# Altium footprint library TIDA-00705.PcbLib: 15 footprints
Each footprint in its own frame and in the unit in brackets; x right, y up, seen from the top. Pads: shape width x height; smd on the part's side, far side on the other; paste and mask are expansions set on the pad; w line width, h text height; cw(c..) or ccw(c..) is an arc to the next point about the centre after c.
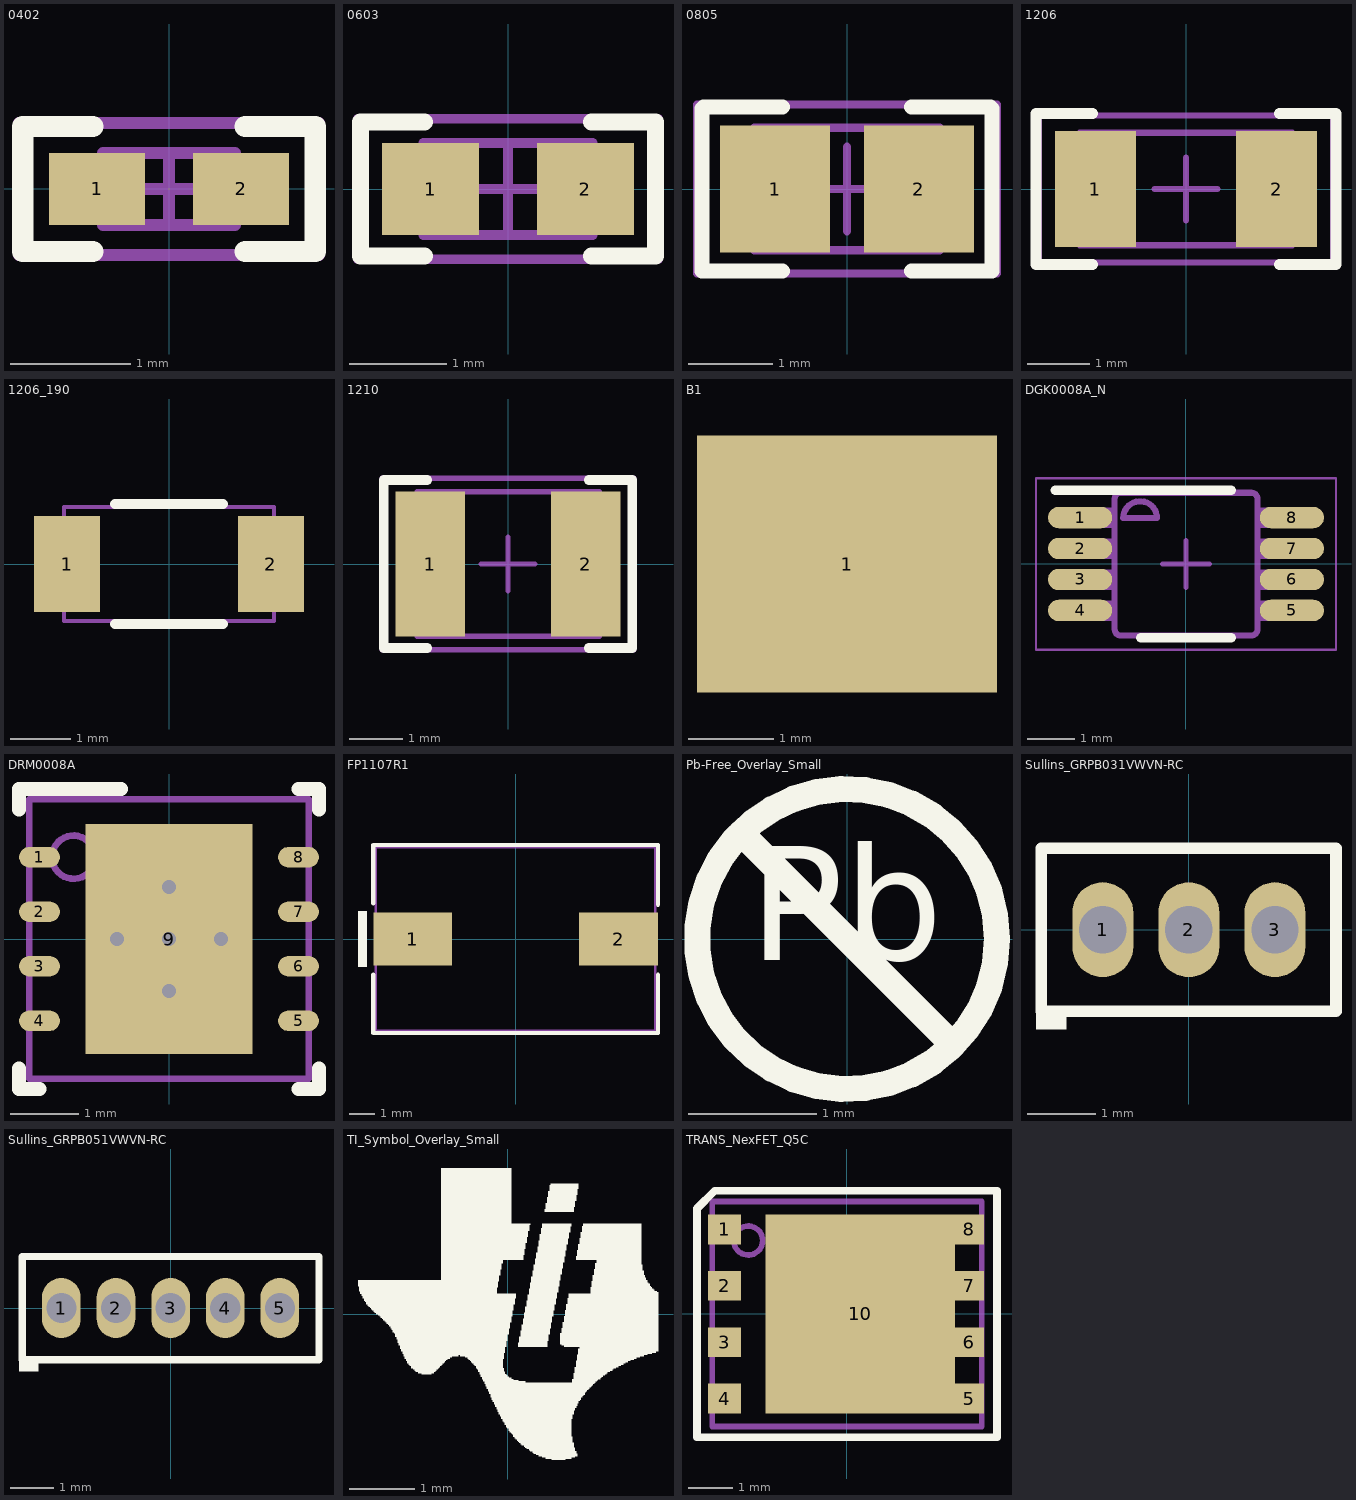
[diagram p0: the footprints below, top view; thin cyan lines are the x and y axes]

## 0402 [mm] "0402 from SM-752 data"
height 0.6
pads (2):
  rect 0.8x0.6 smd: 1(-0.6,0) 2(0.6,0)
Top Overlay:
  lines w0.178: -0.635,-0.521 -1.219,-0.521 -1.219,0.521 -0.635,0.521 ; 0.635,-0.521 1.219,-0.521 1.219,0.521 0.635,0.521
Mechanical 5:
  lines w0.1: -1.25,-0.55 1.25,-0.55 1.25,0.55 -1.25,0.55 -1.25,-0.55
  text ".Designator" at 0.864,0.381 h0.76
Mechanical 13:
  lines w0.1: -0.35,-0.3 -0.35,0.3 ; 0.35,-0.3 0.35,0.3 ; -0.55,-0.3 -0.55,0.3 0.55,0.3 0.55,-0.3 -0.55,-0.3
Mechanical 15:
  lines w0.1: -0.3,0 0.3,0 ; 0,-0.3 0,0.3 ; -1.25,-0.55 -1.25,0.55 1.25,0.55 1.25,-0.55 -1.25,-0.55
3D body: height 0.6, standoff 0, extent -0.549,-0.299 -0.351,0.299
3D body: height 0.6, standoff 0, extent -0.349,-0.299 0.349,0.299
3D body: height 0.6, standoff 0, extent 0.351,-0.299 0.549,0.299

## 0603 [mm] "0603 from SM-752 data"
height 1
pads (2):
  rect 1x0.95 smd: 1(-0.8,0) 2(0.8,0)
Top Overlay:
  lines w0.178: -0.864,-0.691 -1.524,-0.691 -1.524,0.693 -0.864,0.693 ; 0.864,-0.691 1.524,-0.691 1.524,0.693 0.864,0.693
Mechanical 5:
  lines w0.1: -1.55,-0.725 -1.55,0.725 1.55,0.725 1.55,-0.725 -1.55,-0.725
  text ".Designator" at 0.813,0.432 h0.76
Mechanical 13:
  lines w0.1: -0.55,-0.475 -0.55,0.475 ; 0.55,-0.475 0.55,0.475 ; -0.875,-0.475 0.875,-0.475 0.875,0.475 -0.875,0.475 -0.875,-0.475
Mechanical 15:
  lines w0.1: -0.475,0 0.475,0 ; 0,-0.475 0,0.475 ; -1.55,-0.725 1.55,-0.725 1.55,0.725 -1.55,0.725 -1.55,-0.725
3D body: height 1, standoff 0, extent -0.874,-0.474 -0.551,0.474
3D body: height 1, standoff 0, extent -0.549,-0.474 0.549,0.474
3D body: height 1, standoff 0, extent 0.551,-0.474 0.874,0.474

## 0805 [mm] "0805 from SM-752 data"
height 1.45
pads (2):
  rect 1.3x1.5 smd: 1(-0.85,0) 2(0.85,0)
Top Overlay:
  lines w0.178: -0.762,-0.968 -1.717,-0.968 -1.717,0.95 -1.699,0.968 -0.762,0.968 ; 0.762,-0.968 1.717,-0.968 1.717,0.95 1.699,0.968 0.762,0.968
Mechanical 5:
  lines w0.1: -1.775,-1 1.775,-1 1.775,1 -1.775,1 -1.775,-1
  text ".Designator" at 1.041,0.381 h0.76
Mechanical 13:
  lines w0.1: -0.65,-0.725 -0.65,0.725 ; 0.65,-0.725 0.65,0.725 ; -1.1,-0.725 1.1,-0.725 1.1,0.725 -1.1,0.725 -1.1,-0.725
Mechanical 15:
  lines w0.1: -0.5,0 0.5,0 ; 0,-0.5 0,0.5 ; -1.775,-1 1.775,-1 1.775,1 -1.775,1 -1.775,-1
3D body: height 1.45, standoff 0, extent -1.099,-0.724 -0.651,0.724
3D body: height 1.45, standoff 0, extent -0.649,-0.724 0.649,0.724
3D body: height 1.45, standoff 0, extent 0.651,-0.724 1.099,0.724

## 1206 [mm] "1206 from SM-752 data"
height 1.35
pads (2):
  rect 1.3x1.85 smd: 1(-1.45,0) 2(1.45,0)
Top Overlay:
  lines w0.178: -1.5,-1.21 -2.4,-1.21 -2.4,1.21 -1.5,1.21 ; 1.5,-1.21 2.4,-1.21 2.4,1.21 1.5,1.21
Mechanical 5:
  lines w0.1: -1.7,-0.9 -1.7,0.9 1.7,0.9 1.7,-0.9 -1.7,-0.9
  text ".Designator" at 0.991,0.356 h0.76
Mechanical 13:
  lines w0.1: -1.2,-0.9 -1.2,0.9 ; 1.2,-0.9 1.2,0.9 ; -1.7,-0.9 -1.7,0.9 1.7,0.9 1.7,-0.9 -1.7,-0.9
Mechanical 15:
  lines w0.1: -0.5,0 0.5,0 ; 0,-0.5 0,0.5 ; -2.35,-1.175 -2.35,1.175 2.35,1.175 2.35,-1.175 -2.35,-1.175
3D body: height 1.35, standoff 0, extent 1.201,-0.899 1.699,0.899
3D body: height 1.35, standoff 0, extent -1.199,-0.899 1.199,0.899
3D body: height 1.35, standoff 0, extent -1.699,-0.899 -1.201,0.899

## 1206_190 [mm] "1206_190"
height 1.9
pads (2):
  rect 1.1x1.6 smd: 1(-1.7,0) 2(1.7,0)
Top Overlay:
  lines w0.17: -0.9,-1 0.9,-1 ; -0.9,1 0.9,1
Mechanical 5:
  lines w0.07: -1.75,-0.95 -1.75,0.95 1.75,0.95 1.75,-0.95 -1.75,-0.95
  text ".Designator" at 0.635,0.432 h0.76
3D body: height 1.9, standoff 0, extent 1.301,-0.949 1.749,0.949
3D body: height 1.9, standoff 0, extent -1.299,-0.949 1.299,0.949
3D body: height 1.9, standoff 0, extent -1.749,-0.949 -1.301,0.949

## 1210 [mm] "1210 from SM-752 data"
height 1.35
pads (2):
  rect 1.3x2.7 smd: 1(-1.45,0) 2(1.45,0)
Top Overlay:
  lines w0.178: -1.511,-1.568 -2.316,-1.568 -2.316,1.568 -1.511,1.568 ; 1.511,-1.568 2.316,-1.568 2.316,1.568 1.511,1.568
Mechanical 5:
  lines w0.1: -1.7,-1.35 -1.7,1.35 1.7,1.35 1.7,-1.35 -1.7,-1.35
  text ".Designator" at 1.143,0.432 h0.76
Mechanical 13:
  lines w0.1: -1.2,-1.35 -1.2,1.35 ; 1.2,-1.35 1.2,1.35 ; -1.7,-1.35 1.7,-1.35 1.7,1.35 -1.7,1.35 -1.7,-1.35
Mechanical 15:
  lines w0.1: -0.5,0 0.5,0 ; 0,-0.5 0,0.5 ; -2.35,-1.6 2.35,-1.6 2.35,1.6 -2.35,1.6 -2.35,-1.6
3D body: height 1.35, standoff 0, extent 1.201,-1.349 1.699,1.349
3D body: height 1.35, standoff 0, extent -1.199,-1.349 1.199,1.349
3D body: height 1.35, standoff 0, extent -1.699,-1.349 -1.201,1.349

## B1 [mm]
height 1.9
pads (1):
  rect 3.5x3 smd: 1(12.113,-20.422)

## DGK0008A_N [mm] "TSOP, 8-Leads, Body 3x3mm, Pitch 0.65mm, IPC Medium Density"
height 1.1
pads (8):
  oval 1.35x0.45 smd: 1(-2.225,0.975) 2(-2.225,0.325) 3(-2.225,-0.325) 4(-2.225,-0.975) 5(2.225,-0.975) 6(2.225,-0.325) 7(2.225,0.325) 8(2.225,0.975)
Top Overlay:
  lines w0.2: -2.75,1.55 0.95,1.55 ; -0.95,-1.55 0.95,-1.55
Mechanical 5:
  lines w0.127: -2.45,-1.131 -2.21,-1.131 -2.091,-1.131 -2.087,-1.131 -1.784,-1.131 -1.498,-1.131 -1.498,-0.826 -1.784,-0.826 -2.087,-0.826 -2.091,-0.826 -2.21,-0.826 -2.45,-0.826 -2.45,-1.131 ; -2.45,-0.48 -2.21,-0.48 -2.091,-0.48 -2.087,-0.48 -1.784,-0.48 -1.498,-0.48 -1.498,-0.175 -1.784,-0.175 -2.087,-0.175 -2.091,-0.175 -2.21,-0.175 -2.45,-0.175 -2.45,-0.48 ; -2.45,0.17 -2.21,0.17 -2.091,0.17 -2.087,0.17 -1.784,0.17 -1.498,0.17 -1.498,0.475 -1.784,0.475 -2.087,0.475 -2.091,0.475 -2.21,0.475 -2.45,0.475 -2.45,0.17 ; -2.45,0.82 -2.21,0.82 -2.091,0.82 -2.087,0.82 -1.784,0.82 -1.498,0.82 -1.498,1.125 -1.784,1.125 -2.087,1.125 -2.091,1.125 -2.21,1.125 -2.45,1.125 -2.45,0.82 ; -1.497,-1.377 ccw(c-1.37,-1.374) -1.373,-1.501 -1.371,-1.501 1.373,-1.501 1.375,-1.501 ccw(c1.373,-1.374) 1.5,-1.377 1.5,-1.374 1.5,1.369 1.5,1.372 ccw(c1.373,1.369) 1.375,1.496 1.373,1.496 -1.371,1.496 -1.373,1.496 ccw(c-1.37,1.369) -1.497,1.372 -1.498,1.369 -1.498,-1.374 -1.497,-1.377 ; -1.32,0.962 cw(c-0.964,0.962) -0.609,0.962 -1.32,0.962 ; 1.5,-1.131 1.5,-0.826 1.786,-0.826 2.089,-0.826 2.093,-0.826 2.213,-0.826 2.452,-0.826 2.452,-1.131 2.213,-1.131 2.093,-1.131 2.089,-1.131 1.786,-1.131 1.5,-1.131 ; 1.5,-0.48 1.5,-0.175 1.786,-0.175 2.089,-0.175 2.093,-0.175 2.213,-0.175 2.452,-0.175 2.452,-0.48 2.213,-0.48 2.093,-0.48 2.089,-0.48 1.786,-0.48 1.5,-0.48 ; 1.5,0.17 1.5,0.475 1.786,0.475 2.089,0.475 2.093,0.475 2.213,0.475 2.452,0.475 2.452,0.17 2.213,0.17 2.093,0.17 2.089,0.17 1.786,0.17 1.5,0.17 ; 1.5,0.82 1.5,1.125 1.786,1.125 2.089,1.125 2.093,1.125 2.213,1.125 2.452,1.125 2.452,0.82 2.213,0.82 2.093,0.82 2.089,0.82 1.786,0.82 1.5,0.82
  text ".Designator" at -1.15,-0.3 h0.76
Mechanical 15:
  lines w0.05: -3.15,-1.8 3.15,-1.8 3.15,1.8 -3.15,1.8 -3.15,-1.8
  lines w0.1: -0.5,0 0.5,0 ; 0,-0.5 0,0.5
3D body: height 0.96, standoff 0, extent -2.451,-1.499 2.451,1.499

## DRM0008A [mm] "TI"
height 1
pads (9):
  oval 0.6x0.3 smd: 1(-1.9,1.2) 2(-1.9,0.4) 3(-1.9,-0.4) 4(-1.9,-1.2) 5(1.9,-1.2) 6(1.9,-0.4) 7(1.9,0.4) 8(1.9,1.2)
  rect 2.45x3.38 smd paste-1.25: 9(0,0)
via 0,0.762 diameter 0.5 hole 0.2
via -0.762,0 diameter 0.5 hole 0.2
via 0.762,0 diameter 0.5 hole 0.2
via 0,-0.762 diameter 0.5 hole 0.2
via 0,0 diameter 0.5 hole 0.2
Top Overlay:
  lines w0.2: -2.2,-1.9 -2.2,-2.2 -1.9,-2.2 ; -2.2,1.9 -2.2,2.2 -0.7,2.2 ; 1.9,-2.2 2.2,-2.2 2.2,-1.9 ; 1.9,2.2 2.2,2.2 2.2,1.9
Top Paste:
  rectangle: 0.1,0.1 1.184,1.56
  region: -0.1,1.56 -1.184,1.56 -1.184,0.1 -0.1,0.1
  region: -0.1,-0.1 -1.184,-0.1 -1.184,-1.56 -0.1,-1.56
  rectangle: 0.1,-1.56 1.184,-0.1
Mechanical 5:
  circle w0.1: c-1.4,1.2 r0.316
  lines w0.102: -2.05,-2.05 2.05,-2.05 2.05,2.05 -2.05,2.05 -2.05,-2.05
  text ".Designator" at 0.381,-0.359 h0.76
3D body: height 1, standoff 0, extent -2.049,-2.049 2.049,2.049
3D body: height 1.01, standoff 0.8, extent -1.722,0.878 -1.078,1.522

## FP1107R1 [mm] "COILTRONICS"
height 7.5
pads (2):
  rect 3.1x2.1 smd: 1(-4.05,0) 2(4.05,0)
Top Overlay:
  rectangle: -6.2,-1.1 -5.85,1.1
  lines w0.17: -5.6,-1.4 -5.6,-3.7 5.6,-3.7 5.6,-1.4 ; -5.6,1.4 -5.6,3.7 3.3,3.7 5.6,3.7 5.6,1.35
Mechanical 5:
  circle w0.1: c-4.1,0 r0.4
  lines w0.1: -5.5,-3.6 -5.5,3.6 5.5,3.6 5.5,-3.6 -5.5,-3.6
  text ".Designator" at -0.587,0.406 h0.76
3D body: height 7.5, standoff 0, extent -5.499,-3.599 5.499,3.599
3D body: height 7.51, standoff 7, extent -4.507,-0.407 -3.693,0.407

## Pb-Free_Overlay_Small [mm]
height 1.75
Top Overlay:
  circle w0.203: c0,0 r1.168
  lines w0.203: -0.826,0.826 0.826,-0.826
  text "Pb" at -0.762,-0.457 h1.52

## Sullins_GRPB031VWVN-RC [mm] "SULLINS"
height 4.2
pads (3):
  oval 0.9x1.4 hole 0.7: 1(-1.27,0) 2(0,0) 3(1.27,0)
Top Overlay:
  rectangle: -2.255,-1.475 -1.805,-1.225
  lines w0.17: -2.18,-1.2 2.02,-1.2 2.17,-1.2 2.17,0.225 2.17,1.2 -2.18,1.2 -2.18,-1.2
Mechanical 5:
  lines w0.06: -2.155,-1.17 2.17,-1.17 2.17,1.17 -2.155,1.17 -2.155,-1.17
  text ".Designator" at -0.483,-0.381 h0.76
3D body: height 1.2, standoff 0, extent -2.154,-1.169 2.169,1.169
3D body: height 4.2, standoff -2.5, extent -1.47,-0.2 -1.07,0.2
3D body: height 4.2, standoff -2.5, extent -0.2,-0.2 0.2,0.2
3D body: height 4.2, standoff -2.5, extent 1.07,-0.2 1.47,0.2

## Sullins_GRPB051VWVN-RC [mm] "SULLINS"
height 4.2
pads (5):
  oval 0.9x1.4 hole 0.7: 1(-2.54,0) 2(-1.27,0) 3(0,0) 4(1.27,0) 5(2.54,0)
Top Overlay:
  rectangle: -3.525,-1.475 -3.075,-1.225
  lines w0.17: -3.45,-1.2 -3.45,1.2 3.45,1.2 3.45,0.225 3.45,-1.2 0.75,-1.2 -3.45,-1.2
Mechanical 5:
  lines w0.06: -3.425,-1.17 -3.425,1.17 3.425,1.17 3.425,-1.17 -3.425,-1.17
  text ".Designator" at 0.737,0.406 h0.76
3D body: height 4.2, standoff -2.5, extent 2.34,-0.2 2.74,0.2
3D body: height 4.2, standoff -2.5, extent 1.07,-0.2 1.47,0.2
3D body: height 4.2, standoff -2.5, extent -0.2,-0.2 0.2,0.2
3D body: height 4.2, standoff -2.5, extent -1.47,-0.2 -1.07,0.2
3D body: height 4.2, standoff -2.5, extent -2.74,-0.2 -2.34,0.2
3D body: height 1.2, standoff 0, extent -3.424,-1.169 3.424,1.169

## TI_Symbol_Overlay_Small [mm]
height 1.9
Top Overlay:
  drawing of 3 lines, arcs and shapes, not listed

## TRANS_NexFET_Q5C [mm] "TI recommended land pattern (nominal) M0139-01"
height 1.1
pads (9):
  rect 0.75x0.675 smd mask+0.051: 1(-2.776,1.917) 2(-2.776,0.639) 3(-2.776,-0.639) 4(-2.776,-1.917)
  rect 0.655x0.675 smd mask+0.051: 5(2.776,-1.917) 6(2.776,-0.639) 7(2.776,0.639) 8(2.776,1.917)
  rect 4.295x4.51 smd paste-2.2 mask+0.051: 10(0.301,0)
Top Overlay:
  lines w0.178: -3.4,-2.795 0,-2.795 3.4,-2.795 3.4,0 3.4,2.795 0,2.795 -2.995,2.795 -3.4,2.39 -3.4,0 -3.4,-2.795
Top Paste:
  region: 2.349,2.155 0.401,2.155 0.401,0.1 2.349,0.1
  region: -1.746,2.155 0.201,2.155 0.201,0.1 -1.746,0.1
  region: -1.746,-2.155 0.201,-2.155 0.201,-0.1 -1.746,-0.1
  region: 2.349,-2.155 0.401,-2.155 0.401,-0.1 2.349,-0.1
Mechanical 5:
  circle w0.127: c-2.24,1.665 r0.329
  lines w0.127: -3.05,-2.55 -3.05,2.55 3.05,2.55 3.05,-2.55 -3.05,-2.55
  text ".Designator" at 0.737,0.432 h0.76
3D body: height 1.06, standoff 0, extent -3.05,-2.55 3.05,2.55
